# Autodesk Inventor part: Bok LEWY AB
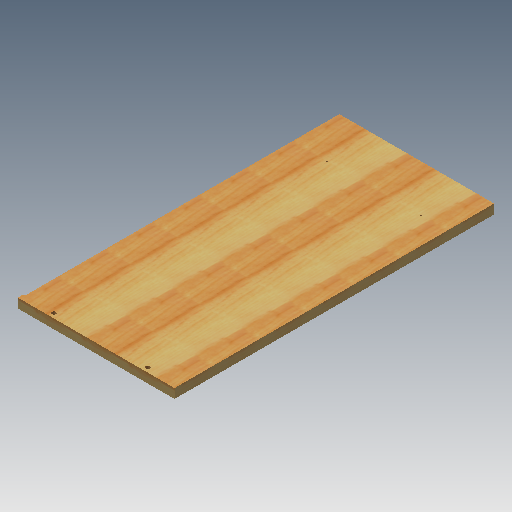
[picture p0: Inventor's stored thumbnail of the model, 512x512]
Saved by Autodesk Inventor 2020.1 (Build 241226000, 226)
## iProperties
Created: 2005-10
Part Number: Bok LEWY AB
Document SubType Name: Modeling
Designer: F.Stasiak
Density: 1 g/cm^3
Material: Ogólny
Appearance: Drewno (sosna)
Manager: www.cadconsulting.pl
Company: Fabian Stasiak CAD Consulting
Author: F.Stasiak
Subject: Zbiór ćwiczeń. Autodesk Inventor 2020. Kurs podstawowy
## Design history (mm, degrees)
sketch "Szkic1"
  geometry: L1 (-150, 9)-(150, 9); L2 (150, 9)-(150, -9); L3 (150, -9)-(-150, -9); L4 (-150, -9)-(-150, 9); L5 (0, 9)-(0, -9); L6 (-150, 1)-(-146.5, 1); L7 (-146.5, 1)-(-146.5, 9); L8 (150, 0)-(-150, 0); 5 further points
  constraints: 16 end point, 5 midpoint, 5 point on line, 3 perpendicular, 2 parallel, 1 coincident, 1 horizontal
  dimensions: "d0" = 300 distance of L2.end L3.end; "d1" = 18 distance of L1.end L2.end; "d2" = 3.5 distance of L6.start L6.end; "d3" = 8 distance of L6.end L7.end; "d8" = 97 distance of point (107, 0) point (10, 0); "d9" = 130 distance of point (-120, 0) point (10, 0); "d10" = 30 distance from line of L4 point (-120, 0)
extrude "Wyciągnięcie proste1" new body sketch "Szkic1" distance "d4" = 612; taper "d5" = 0 deg
extrude "Wyciągnięcie proste2" cut sketch "Szkic1" distance "d6" = 602 (computed from d4); taper "d7" = 0 deg
hole "Otwór1" sketch "Szkic1" diameter "d11" = 8; stored, may be unused: drill point angle "d13" = 118 deg, countersink angle "d43" = 90 deg; dims "d12" = 25, "d40" = 6, "d41" = 4, "d42" = 2
sketch "Szkic2"
  geometry: L1 (0, 0)-(300, 0) reference; L2 (300, 612)-(300, 0) reference; L3 (0, 10)-(0, 0) reference; L4 (300, 9)-(0, 9); 2 further points
  constraints: 4 point on line, 2 end point, 1 horizontal
  dimensions: "d14" = 9 distance between parallel lines of L1 L4; "d15" = 60 distance from line of L2 point (240, 9); "d16" = 180 distance of point (60, 9) point (240, 9)
hole "Otwór2" sketch "Szkic2" at (240, 9), (60, 9) diameter "d17" = 8; stored, may be unused: drill point angle "d19" = 118 deg, countersink angle "d47" = 90 deg; dims "d18" = 14, "d44" = 6, "d45" = 4, "d46" = 2
sketch "Szkic3"
  geometry: L1 (300, 612)-(3.5, 612) reference; L2 (300, 612)-(300, 0) reference; L3 (300, 522)-(70, 522); 2 further points
  constraints: 2 end point, 2 point on line, 1 coincident, 1 perpendicular
  dimensions: "d20" = 180 distance of point (70, 522) point (250, 522); "d21" = 50 distance from line of L2 point (250, 522); "d22" = 90 distance between parallel lines of L1 L3
hole "Otwory pod szynę" sketch "Szkic3" at (70, 522), (250, 522) diameter "d23" = 3; stored, may be unused: drill point angle "d25" = 118 deg, countersink angle "d35" = 90 deg; dims "d24" = 10, "d34" = 2, "d38" = 6, "d39" = 4
node "Bryła1"
node "Korpusy bryłowe"
node "Korpusy powierzchniowe"
